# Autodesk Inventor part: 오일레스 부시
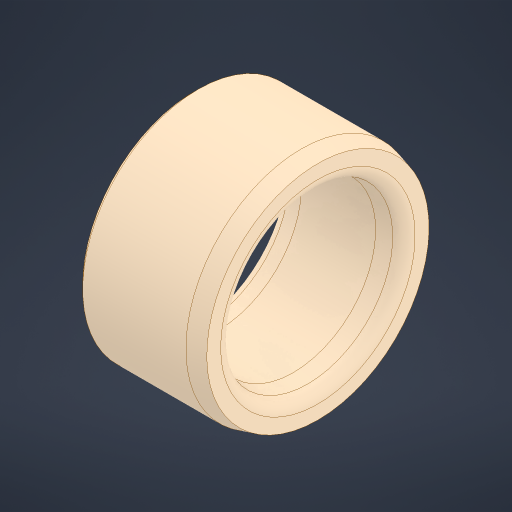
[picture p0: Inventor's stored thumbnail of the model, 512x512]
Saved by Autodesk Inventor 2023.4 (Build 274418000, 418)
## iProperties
Created: 2024-05
Part Number: 오일레스 부시
Material: 구리, 합금
Document SubType Name: Modeling
Designer: Edu03
Density: 8.92 g/cm^3
Appearance: 기본값
Sending System: Autodesk Inventor 2025
Preprocessor: ST-DEVELOPER v20
Author: jhkim
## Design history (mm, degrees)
node "오일레스 부시1"
node "솔리드2"
node "솔리드1"
